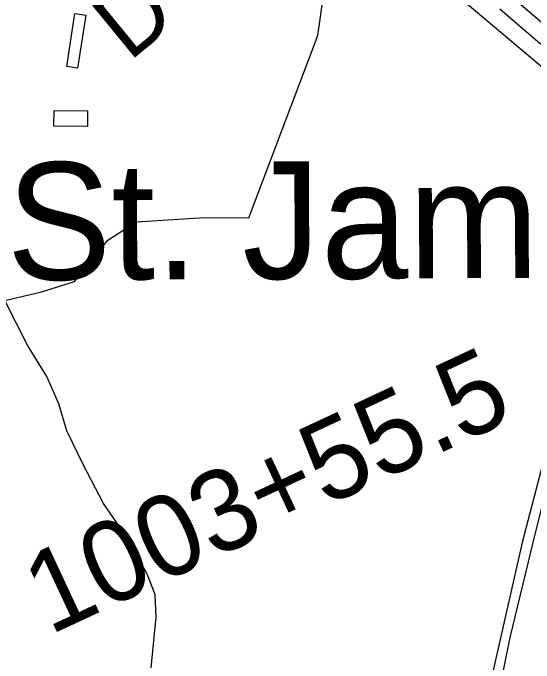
# Model space of a CAD drawing. Extents: x 3424494 to 3462436, y 522220 to 547718.
# Drawn here: x 3439589 to 3440232, y 537838 to 538640 of the extents above; entities that cross this region are included whole.
import ezdxf

# ---------------------------------------------------------------- set-up
doc = ezdxf.new("R2010")
doc.units = 0
for name, color, linetype in [('V-BLDG-OTLN', 7, 'Continuous'), ('V-DTCH-CNTR', 7, 'Continuous'), ('V-RIVR-RANG-IDEN', 7, 'Continuous'), ('V-ROAD-CNTR', 7, 'Continuous'), ('V-SITE-VEGE', 7, 'Continuous'), ('V-SURV-IDEN', 7, 'Continuous'), ('V-TOPO-GNAM-IDEN', 7, 'Continuous'), ('V-TOPO-SHOR', 7, 'Continuous')]:
    doc.layers.add(name, color=color, linetype=linetype)

msp = doc.modelspace()

# ---------------------------------------------------------------- linework, layer by layer
at = {"layer": 'V-BLDG-OTLN'}
for points in [[(3439664.89, 538639.73), (3439678.3, 538637.68), (3439668.29, 538572.17), (3439654.88, 538574.21)], [(3439639.14, 538520.05), (3439680.65, 538519.66), (3439680.46, 538500.07), (3439638.96, 538500.46)]]:
    msp.add_lwpolyline(points, close=True, dxfattribs=at)
at = {"layer": 'V-DTCH-CNTR'}
msp.add_lwpolyline([(3440144.33, 537598), (3440170.92, 537715.06), (3440202.2, 537869.26), (3440234.34, 538001.88), (3440269.2, 538139.67), (3440300.61, 538237.02), (3440333.71, 538321.28), (3440359.6, 538372.35), (3440369.57, 538380.64), (3440384.06, 538386.22), (3440428.32, 538378.12), (3440481.32, 538350.24), (3440523.13, 538318.67), (3440536.39, 538296.18), (3440520.07, 538233.8), (3440494.1, 538114.77), (3440462.19, 537961.89), (3440437.81, 537825.19), (3440411.71, 537700.28), (3440391.34, 537600.09)], dxfattribs=at)
at = {"layer": 'V-ROAD-CNTR'}
msp.add_lwpolyline([(3432086.35, 545626.63), (3433017.49, 544826.15), (3436584.01, 541768.29), (3439656.25, 539130.43), (3440791.29, 538157.35)], dxfattribs=at)
at = {"layer": 'V-SITE-VEGE'}
for points in [[(3439759.13, 537831.64), (3439765.13, 537894.46), (3439763.91, 537922.41), (3439754.29, 537947.61), (3439732.21, 537988.27), (3439700.37, 538034.57), (3439675.54, 538082.22), (3439654.85, 538124.27), (3439645.29, 538157.85), (3439630.14, 538191.48), (3439606.28, 538230.24), (3439578.5, 538285.24), (3439623.8, 538296.21), (3439664.46, 538308.98), (3439705.48, 538360), (3439740.39, 538382.67), (3439825.11, 538387.72), (3439879.53, 538387.45), (3439964.55, 538612.76), (3439989.9, 538789.97)], [(3440143.62, 538656.68), (3440321.24, 538506.74), (3440418.9, 538417.56), (3440429.89, 538393.95), (3440374.1, 538410.41), (3440344.51, 538377.42), (3440286.29, 538255.74), (3440268.48, 538183.18), (3440216.93, 537986.54), (3440155.11, 537714.54)]]:
    msp.add_lwpolyline(points, dxfattribs=at)
at = {"layer": 'V-TOPO-SHOR'}
msp.add_lwpolyline([(3440189.59, 538645.42), (3440239.36, 538602.63), (3440275.77, 538568.24), (3440317.38, 538533.16), (3440340.72, 538511.6), (3440376.93, 538476.83), (3440433.15, 538428.5), (3440473.63, 538394.6), (3440525.57, 538353.9), (3440564.57, 538323.32), (3440603.68, 538288.48), (3440628.48, 538263.42)], dxfattribs=at)

# ---------------------------------------------------------------- texts
at = {"layer": 'V-RIVR-RANG-IDEN'}
msp.add_text('D-020', height=83, rotation=39.34433, dxfattribs=at).set_placement((3439731.9, 538579.54))
at = {"layer": 'V-SURV-IDEN'}
msp.add_text('1003+55.5', height=100, rotation=25.01656, dxfattribs=at).set_placement((3439633.53, 537871.63))
at = {"layer": 'V-TOPO-GNAM-IDEN'}
msp.add_text('St. James', height=145, rotation=0.22245, dxfattribs=at).set_placement((3439580.81, 538310.76))

doc.saveas('drawing.dxf')
